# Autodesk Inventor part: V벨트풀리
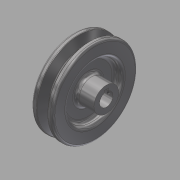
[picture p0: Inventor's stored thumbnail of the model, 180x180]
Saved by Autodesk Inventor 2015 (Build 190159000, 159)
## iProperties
Created: 2015-11
Part Number: V벨트풀리
Material: 강철, 탄소
Document SubType Name: Modeling
Designer: mduedu
Density: 1 g/cm^3
Appearance: 반광택
Author: mduedu
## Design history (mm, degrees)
sketch "스케치1"
  geometry: L1 (-9.5, 0)-(9.5, 0); L2 (0, 0)-(0, 37.7); L3 (-4.825, 37.7)-(-9.5, 37.7); L4 (-9.5, 37.7)-(-9.5, 0); L5 (0, 28.7)-(-2.074, 28.7); L6 (-2.074, 28.7)-(-4.825, 37.7); L7 (4.825, 37.7)-(9.5, 37.7); L8 (9.5, 37.7)-(9.5, 0); L9 (0, 28.7)-(2.074, 28.7); L10 (2.074, 28.7)-(4.825, 37.7); L11 (-9.5, 35)-(9.5, 35); 3 further points
  constraints: 22 end point, 7 point on line, 4 perpendicular, 3 symmetric about line, 1 coincident, 1 horizontal, 1 horizontal alignment, 1 midpoint, 1 vertical
  dimensions: "d0" = 19 distance of L1.start L1.end; "d2" = 75.4 diameter of L2.end L1 (derived); "d3" = 34 deg angle of L10 L6; "d4" = 6.3 distance between parallel lines of L11 L9; "d5" = 2.7 distance between parallel lines of L7 L11; "d6" = 8 distance of point (4, 35) point (-4, 35); "d7" = 70 diameter of L11 L1
revolve "회전1" sketch "스케치1" stored, may be unused: angle "d8" = 90 deg
sketch "스케치2"
  geometry: C1 r 24 at (0, 0); C2 r 11 at (0, 0); 1 further point
  constraints: 2 centre point, 2 coincident
  dimensions: "d9" = 48 diameter of C1; "d10" = 22 diameter of C2
extrude "돌출1" cut sketch "스케치2" distance "d11" = 6; taper "d12" = 0 deg
extrude "돌출3" join sketch "스케치2" distance "d37" = 10; taper "d38" = 0 deg
fillet "모깎기1" dims "d13" = 3
fillet "모깎기2" dims "d14" = 3
fillet "모깎기3" dims "d15" = 1, "d16" = 0.5, "d17" = 2
hole "구멍1" diameter "d20" = 12; stored, may be unused: countersink angle "d24" = 90 deg, drill point angle "d26" = 118 deg; dims "d21" = 6, "d22" = 4, "d23" = 2, "d25" = 8, "d39" = 10, "d40" = 10
sketch "스케치3"
  geometry: L1 (-2, 0)-(2, 0); L2 (2, 0)-(2, 7.8); L3 (2, 7.8)-(-2, 7.8); L4 (-2, 7.8)-(-2, 0); 2 further points
  constraints: 8 end point, 2 parallel, 1 coincident, 1 horizontal, 1 midpoint, 1 perpendicular
  dimensions: "d27" = 4 distance of L2.end L3.end; "d29" = 7.8 distance of L3.end L1.start
extrude "돌출2" cut sketch "스케치3" stored distance "d30" = 6; taper "d31" = 0 deg
chamfer "모따기1" distance "d32" = 0.5; stored, may be unused: second distance "d33" = 2, angle "d34" = 45 deg
node "작업 평면1"
sketch "스케치4"
  geometry: L1 (-19, 11)-(-19, -11) reference; 2 further points
  constraints: 1 horizontal alignment
  dimensions: "d41" = 25 distance from line of point (6, 0) L1
hole "구멍2" sketch "스케치4" at (6, 0) diameter "d42" = 2.459; stored, may be unused: countersink angle "d46" = 90 deg, drill point angle "d48" = 118 deg; dims "d43" = 6, "d44" = 4, "d45" = 2, "d47" = 8
node "솔리드1"
mirror "대칭1"
